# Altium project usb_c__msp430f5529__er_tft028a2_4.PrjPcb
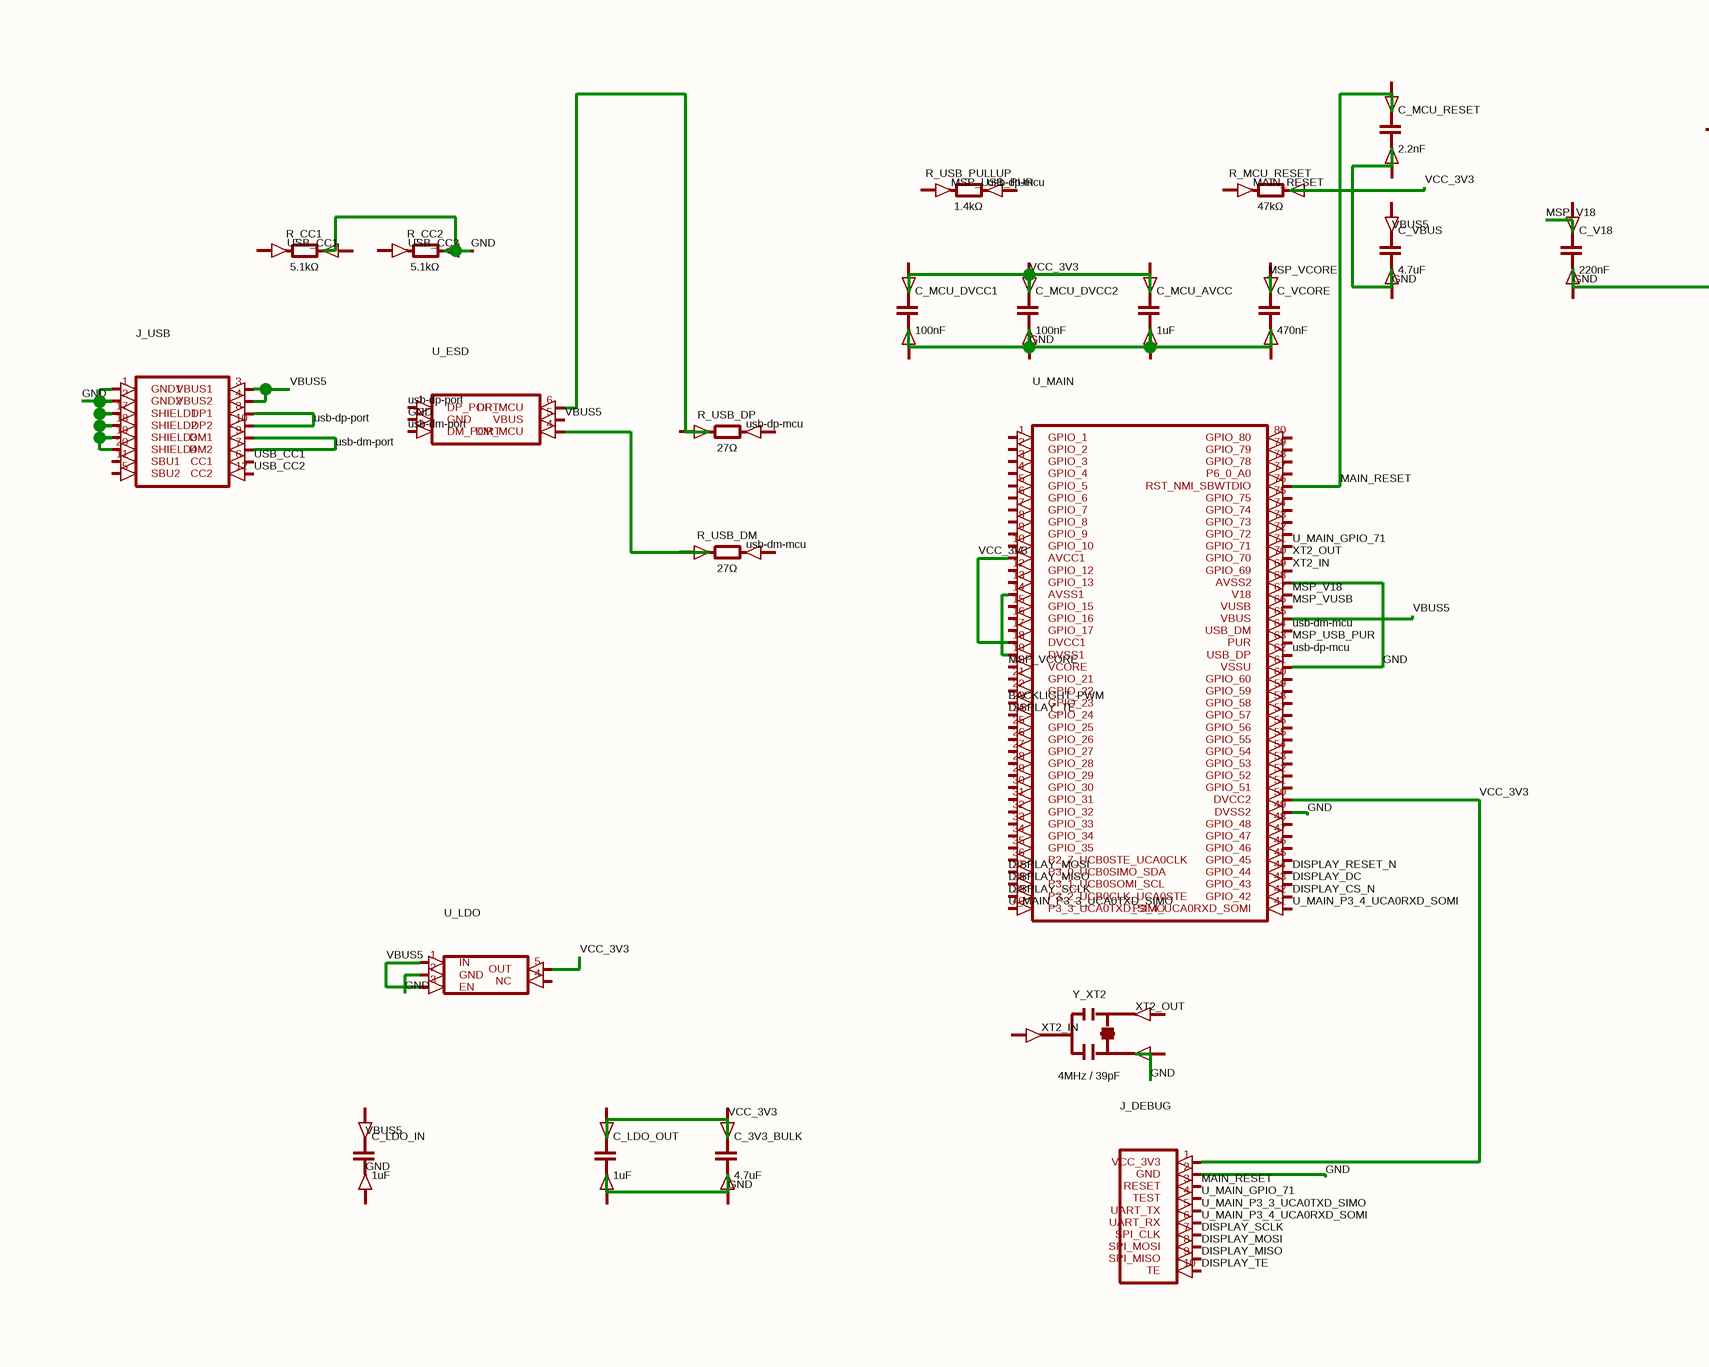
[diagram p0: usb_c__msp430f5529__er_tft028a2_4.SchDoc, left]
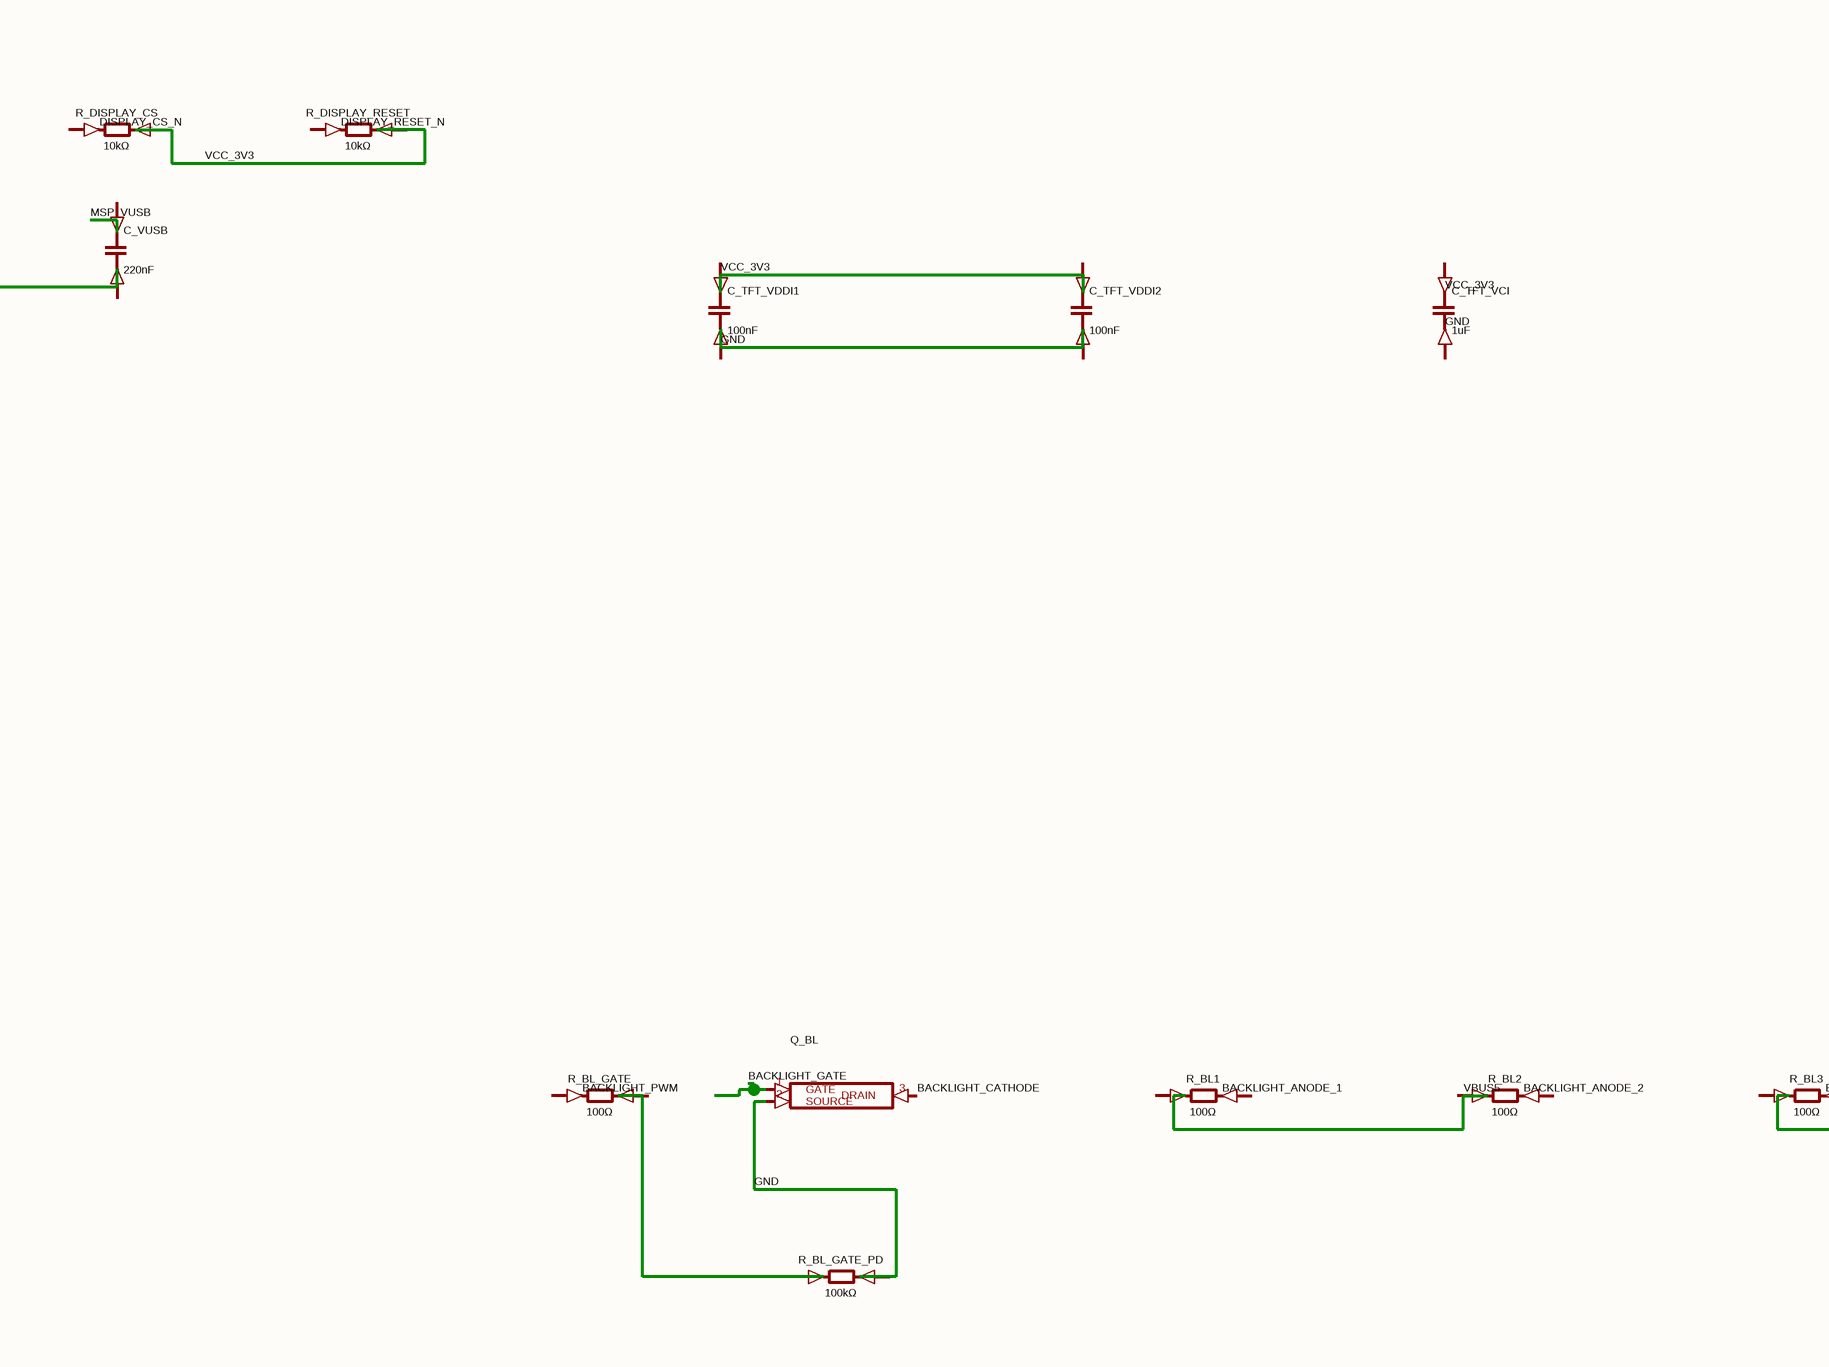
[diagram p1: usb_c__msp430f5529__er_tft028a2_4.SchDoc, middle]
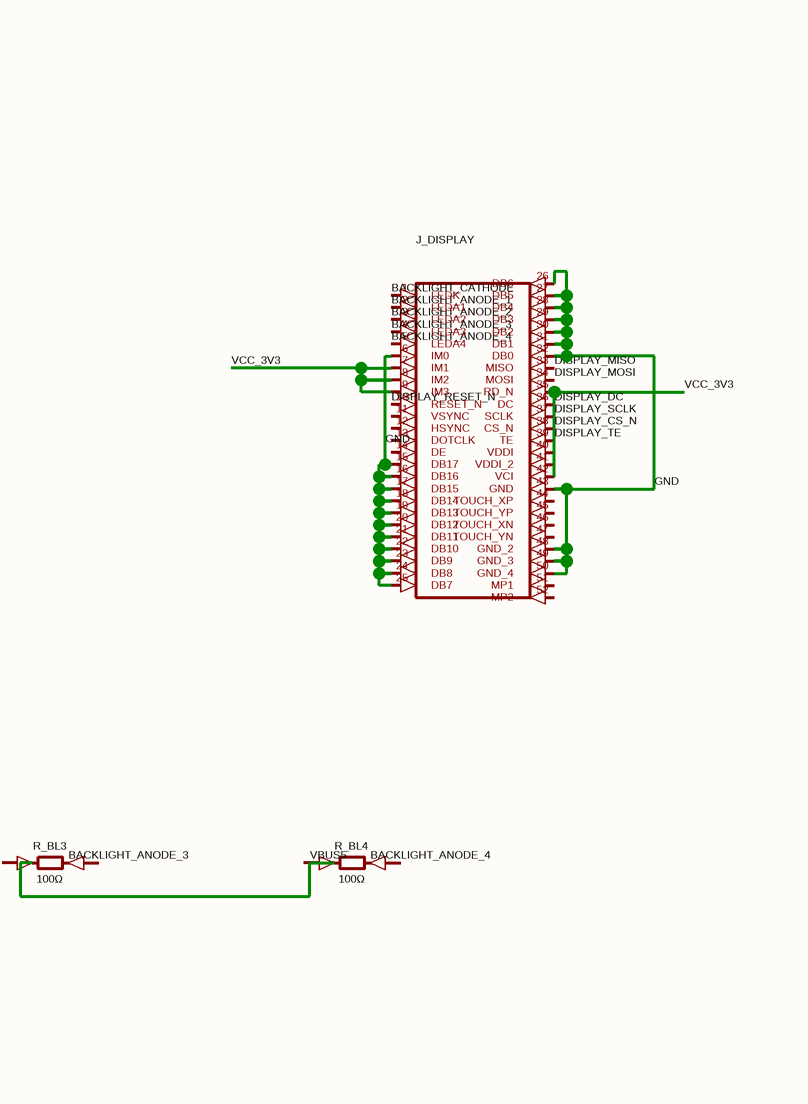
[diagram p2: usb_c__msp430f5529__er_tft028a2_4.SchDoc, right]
1 sheet, 36 parts. Net scope: global (net labels, ports and power ports of the same name join across sheets).
Board file: usb_c__msp430f5529__er_tft028a2_4.PcbDoc

## Sheet usb_c__msp430f5529__er_tft028a2_4.SchDoc
size 387 x 150 mm

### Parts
C_3V3_BULK  4.7uF
C_LDO_IN  1uF
C_LDO_OUT  1uF
C_MCU_AVCC  1uF
C_MCU_DVCC1  100nF
C_MCU_DVCC2  100nF
C_MCU_RESET  2.2nF
C_TFT_VCI  1uF
C_TFT_VDDI1  100nF
C_TFT_VDDI2  100nF
C_V18  220nF
C_VBUS  4.7uF
C_VCORE  470nF
C_VUSB  220nF
J_DEBUG  (no value)
J_DISPLAY  (no value)
J_USB  (no value)
Q_BL  (no value)
R_BL1  100Ω
R_BL2  100Ω
R_BL3  100Ω
R_BL4  100Ω
R_BL_GATE  100Ω
R_BL_GATE_PD  100kΩ
R_CC1  5.1kΩ
R_CC2  5.1kΩ
R_DISPLAY_CS  10kΩ
R_DISPLAY_RESET  10kΩ
R_MCU_RESET  47kΩ
R_USB_DM  27Ω
R_USB_DP  27Ω
R_USB_PULLUP  1.4kΩ
U_ESD  (no value)
U_LDO  (no value)
U_MAIN  (no value)
Y_XT2  4MHz / 39pF

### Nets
BACKLIGHT_ANODE_1: J_DISPLAY.2(LEDA1)
BACKLIGHT_ANODE_2: J_DISPLAY.3(LEDA2)
BACKLIGHT_ANODE_3: J_DISPLAY.4(LEDA3)
BACKLIGHT_ANODE_4: J_DISPLAY.5(LEDA4)
BACKLIGHT_CATHODE: J_DISPLAY.1(LEDK) Q_BL.3(DRAIN)
BACKLIGHT_GATE: Q_BL.1(GATE)
BACKLIGHT_PWM: U_MAIN.23(GPIO_23)
DISPLAY_CS_N: J_DEBUG.1(VCC_3V3) J_DEBUG.2(GND) J_DEBUG.7(SPI_CLK) J_DEBUG.10(TE) J_DISPLAY.6(IM0) J_DISPLAY.7(IM1) J_DISPLAY.8(IM2) J_DISPLAY.9(IM3) J_DISPLAY.15(DB17) J_DISPLAY.16(DB16) J_DISPLAY.17(DB15) J_DISPLAY.18(DB14) J_DISPLAY.19(DB13) J_DISPLAY.20(DB12) J_DISPLAY.21(DB11) J_DISPLAY.22(DB10) J_DISPLAY.23(DB9) J_DISPLAY.24(DB8) J_DISPLAY.25(DB7) J_DISPLAY.26(DB6) J_DISPLAY.27(DB5) J_DISPLAY.28(DB4) J_DISPLAY.29(DB3) J_DISPLAY.30(DB2) J_DISPLAY.31(DB1) J_DISPLAY.32(DB0) J_DISPLAY.35(RD_N) J_DISPLAY.36(DC) J_DISPLAY.37(SCLK) J_DISPLAY.38(CS_N) J_DISPLAY.39(TE) J_DISPLAY.40(VDDI) J_DISPLAY.41(VDDI_2) J_DISPLAY.42(VCI) J_DISPLAY.43(GND) J_DISPLAY.48(GND_2) J_DISPLAY.49(GND_3) J_DISPLAY.50(GND_4) J_USB.1(GND1) J_USB.2(GND2) J_USB.3(VBUS1) J_USB.4(VBUS2) J_USB.17(SHIELD1) J_USB.18(SHIELD2) J_USB.19(SHIELD3) J_USB.20(SHIELD4) Q_BL.2(SOURCE) R_BL_GATE_PD.2(cathode) R_DISPLAY_CS.2(cathode) R_DISPLAY_RESET.2(cathode) R_MCU_RESET.2(cathode) U_ESD.2(GND) U_ESD.5(VBUS) U_LDO.1(IN) U_LDO.2(GND) U_LDO.3(EN) U_LDO.5(OUT) U_MAIN.11(AVCC1) U_MAIN.14(AVSS1) U_MAIN.18(DVCC1) U_MAIN.19(DVSS1) U_MAIN.24(GPIO_24) U_MAIN.39(P3_2_UCB0CLK_UCA0STE) U_MAIN.42(GPIO_42) U_MAIN.43(GPIO_43) U_MAIN.49(DVSS2) U_MAIN.50(DVCC2) U_MAIN.61(VSSU) U_MAIN.65(VBUS) U_MAIN.68(AVSS2)  [also labelled DISPLAY_DC, DISPLAY_SCLK, DISPLAY_TE, GND, VBUS5, VCC_3V3]
DISPLAY_MISO: J_DEBUG.9(SPI_MISO) J_DISPLAY.33(MISO) U_MAIN.38(P3_1_UCB0SOMI_SCL)
DISPLAY_MOSI: J_DEBUG.8(SPI_MOSI) J_DISPLAY.34(MOSI) U_MAIN.37(P3_0_UCB0SIMO_SDA)
DISPLAY_RESET_N: J_DISPLAY.10(RESET_N) U_MAIN.44(GPIO_44)
MAIN_RESET: J_DEBUG.3(RESET) U_MAIN.76(RST_NMI_SBWTDIO)
MSP_USB_PUR: U_MAIN.63(PUR)
MSP_V18: U_MAIN.67(V18)
MSP_VCORE: U_MAIN.20(VCORE)
MSP_VUSB: U_MAIN.66(VUSB)
U_MAIN_GPIO_71: J_DEBUG.4(TEST) U_MAIN.71(GPIO_71)
U_MAIN_P3_3_UCA0TXD_SIMO: J_DEBUG.5(UART_TX) U_MAIN.40(P3_3_UCA0TXD_SIMO)
U_MAIN_P3_4_UCA0RXD_SOMI: J_DEBUG.6(UART_RX) U_MAIN.41(P3_4_UCA0RXD_SOMI)
usb-dm-mcu: U_MAIN.64(USB_DM)
usb-dm-port: J_USB.7(DM2) J_USB.9(DM1) U_ESD.3(DM_PORT)
usb-dp-mcu: U_MAIN.62(USB_DP)
usb-dp-port: J_USB.8(DP1) J_USB.10(DP2) U_ESD.1(DP_PORT)
USB_CC1: J_USB.6(CC1)
USB_CC2: J_USB.12(CC2)
XT2_IN: U_MAIN.69(GPIO_69)
XT2_OUT: U_MAIN.70(GPIO_70)
NetR_USB_DM_1: R_USB_DM.1(anode) U_ESD.4(DM_MCU)

Not connected (* = marked no-connect by the designer): C_3V3_BULK 1(anode) 2(cathode); C_LDO_IN 1(anode) 2(cathode); C_LDO_OUT 1(anode) 2(cathode); C_MCU_AVCC 1(anode) 2(cathode); C_MCU_DVCC1 1(anode) 2(cathode); C_MCU_DVCC2 1(anode) 2(cathode); C_MCU_RESET 1(anode) 2(cathode); C_TFT_VCI 1(anode) 2(cathode); C_TFT_VDDI1 1(anode) 2(cathode); C_TFT_VDDI2 1(anode) 2(cathode); C_V18 1(anode) 2(cathode); C_VBUS 1(anode) 2(cathode); C_VCORE 1(anode) 2(cathode); C_VUSB 1(anode) 2(cathode); J_DISPLAY 11(VSYNC) 12(HSYNC) 13(DOTCLK) 14(DE) 44(TOUCH_XP) 45(TOUCH_YP) 46(TOUCH_XN) 47(TOUCH_YN) 51(MP1) 52(MP2); J_USB 5(SBU2) 11(SBU1); R_BL1 1(anode) 2(cathode); R_BL2 1(anode) 2(cathode); R_BL3 1(anode) 2(cathode); R_BL4 1(anode) 2(cathode); R_BL_GATE 1(anode) 2(cathode); R_BL_GATE_PD 1(anode); R_CC1 1(anode) 2(cathode); R_CC2 1(anode) 2(cathode); R_DISPLAY_CS 1(anode); R_DISPLAY_RESET 1(anode); R_MCU_RESET 1(anode); R_USB_DM 2(cathode); R_USB_DP 1(anode) 2(cathode); R_USB_PULLUP 1(anode) 2(cathode); U_ESD 6(DP_MCU); U_LDO 4(NC); U_MAIN 1(GPIO_1) 2(GPIO_2) 3(GPIO_3) 4(GPIO_4) 5(GPIO_5) 6(GPIO_6) 7(GPIO_7) 8(GPIO_8) 9(GPIO_9) 10(GPIO_10) 12(GPIO_12) 13(GPIO_13) 15(GPIO_15) 16(GPIO_16) 17(GPIO_17) 21(GPIO_21) 22(GPIO_22) 25(GPIO_25) 26(GPIO_26) 27(GPIO_27) 28(GPIO_28) 29(GPIO_29) 30(GPIO_30) 31(GPIO_31) 32(GPIO_32) 33(GPIO_33) 34(GPIO_34) 35(GPIO_35) 36(P2_7_UCB0STE_UCA0CLK) 45(GPIO_45) 46(GPIO_46) 47(GPIO_47) 48(GPIO_48) 51(GPIO_51) 52(GPIO_52) 53(GPIO_53) 54(GPIO_54) 55(GPIO_55) 56(GPIO_56) 57(GPIO_57) 58(GPIO_58) 59(GPIO_59) 60(GPIO_60) 72(GPIO_72) 73(GPIO_73) 74(GPIO_74) 75(GPIO_75) 77(P6_0_A0) 78(GPIO_78) 79(GPIO_79) 80(GPIO_80); Y_XT2 1(pin1) 2(pin2) 3(pin3)

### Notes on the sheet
- Labels drawn without touching a wire or pin: BACKLIGHT_ANODE_1, BACKLIGHT_ANODE_2, BACKLIGHT_ANODE_3, BACKLIGHT_ANODE_4, BACKLIGHT_PWM, DISPLAY_CS_N, DISPLAY_RESET_N, GND, MAIN_RESET, MSP_USB_PUR, usb-dm-mcu, usb-dp-mcu, USB_CC1, USB_CC2, VBUS5, VCC_3V3, XT2_IN, XT2_OUT

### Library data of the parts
C_3V3_BULK C_LDO_IN C_LDO_OUT C_MCU_AVCC C_MCU_DVCC1 C_MCU_DVCC2 C_MCU_RESET C_TFT_VCI C_TFT_VDDI1 C_TFT_VDDI2 C_V18 C_VBUS C_VCORE C_VUSB = capacitor_down
J_DEBUG = J_DEBUG
J_DISPLAY = J_DISPLAY
J_USB = J_USB
Q_BL = Q_BL
R_BL1-R_BL4 R_BL_GATE R_BL_GATE_PD R_CC1 R_CC2 R_DISPLAY_CS R_DISPLAY_RESET R_MCU_RESET R_USB_DM R_USB_DP R_USB_PULLUP = boxresistor_right
U_ESD = U_ESD
U_LDO = U_LDO
U_MAIN = U_MAIN
Y_XT2 = resonator_right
